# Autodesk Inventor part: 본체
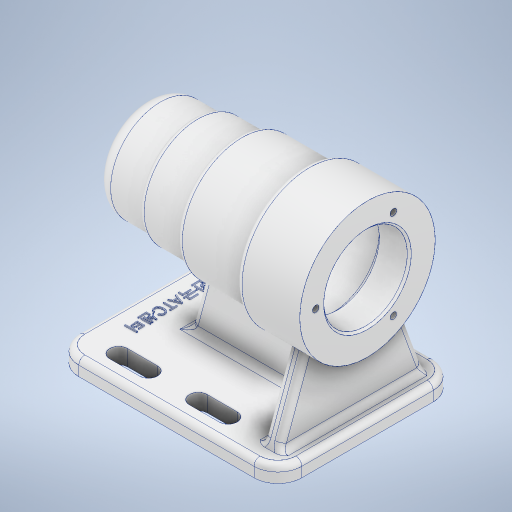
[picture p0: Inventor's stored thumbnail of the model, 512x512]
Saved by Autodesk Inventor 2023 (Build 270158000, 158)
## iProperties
Created: 2022-07
Part Number: 본체
Material: 알루미늄 6061
Document SubType Name: Modeling
Designer: owner
Density: 2.7 g/cm^3
Appearance: 알루미늄 - 평지
Author: owner
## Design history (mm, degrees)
sketch "스케치2"
  geometry: L1 (56, 34)-(24, 34); L2 (24, 34)-(24, 30); L3 (24, 30)-(-10, 30); L4 (-10, 30)-(-10, 27); L5 (-10, 27)-(-32, 27); L6 (-32, 27)-(-32, 25); L7 (-32, 25)-(-56, 25); L8 (-56, 0)-(56, 0); L9 (-56, 25)-(-56, 0); L10 (56, 34)-(56, 0); 4 further points
  constraints: 20 end point, 6 perpendicular, 3 midpoint, 2 coincident, 2 horizontal, 2 vertical
  dimensions: "d0" = 112 distance between parallel lines of L10 L9; "d1" = 80 distance from line of L9 point (24, 32); "d2" = 46 distance from line of L9 point (-10, 28.5); "d3" = 24 distance between parallel lines of L9 L6; "d4" = 68 diameter of L1 L8; "d5" = 60 diameter of L3 L8; "d6" = 54 diameter of L5 L8; "d7" = 50 diameter of L7 L8
revolve "회전1" sketch "스케치2" stored, may be unused: angle "d8" = 90 deg
sketch "스케치3"
  geometry: L1 (56, -34)-(56, 34) reference; L2 (56, 21)-(41, 21); L3 (41, 21)-(41, 24); L4 (41, 24)-(-13, 24); L5 (-13, 24)-(-13, 21); L6 (-13, 21)-(-25, 21); L7 (-25, 21)-(-25, 17.5); L8 (-25, 17.5)-(-43, 17.5); L9 (-55.978, 0)-(56, 0); L10 (-43, 17.5)-(-43, 16); L11 (-43, 16)-(-47, 16); L12 (-47, 16)-(-47, 10.5); L13 (-47, 10.5)-(-50, 10.5); L14 (-50, 10.5)-(-50, 0); 2 further points
  constraints: 26 end point, 9 perpendicular, 2 vertical, 1 horizontal, 1 midpoint, 1 point on line
  dimensions: "d9" = 15 distance of L2.start L2.end; "d10" = 54 distance of L3.end L4.end; "d11" = 12 distance of L5.end L6.end; "d12" = 18 distance of L7.end L8.end; "d13" = 42 diameter of L2 L9; "d16" = 48 diameter of L4 L9; "d19" = 35 diameter of L8 L9; "d20" = 42 diameter of L6 L9; "d21" = 21 diameter of L13 L9; "d22" = 32 diameter of L11 L9; "d23" = 3 distance of L12.end L13.end; "d24" = 4 distance of L10.end L11.end
revolve "회전2" sketch "스케치3" stored, may be unused: angle "d25" = 90 deg
node "작업 평면1"
sketch "스케치4"
  geometry: L1 (56, -45)-(-56, -45); L2 (-56, -45)-(-56, 45); L3 (-56, 45)-(56, 45); L4 (56, 45)-(56, -45); L5 (56, -45)-(-56, 45); L6 (-56, -45)-(56, 45); 1 further point
  constraints: 12 end point, 2 midpoint, 2 parallel, 1 horizontal, 1 perpendicular
  dimensions: "d27" = 112 distance of L2.end L3.end; "d28" = 90 distance of L1.end L2.end
extrude "돌출1" join sketch "스케치4" distance "d29" = 8; taper "d30" = 0 deg
node "작업 평면3"
sketch "스케치8"
  geometry: L1 (-23.409, -24.658)-(-37, -62); L2 (45, -62)-(-45, -62) reference; L3 (37, -62)-(23.409, -24.658); L4 (-37, -62)-(37, -62); L5 (45, -70)-(45, -62) reference; 6 further points
  constraints: 6 end point, 2 midpoint, 1 coincident, 1 collinear, 1 equal length, 1 point on line, 2 other
  dimensions: "d32" = 110 deg angle of L2 L3; "d33" = 110 deg angle of L2 L1; "d34" = 8 distance from line of L3.start L5
extrude "돌출2" join sketch "스케치8" distance "d35" = 8; taper "d36" = 0 deg
sketch "스케치11"
  geometry: L1 (48, -62)-(48, -24.658) reference; L2 (-10, -30)-(24, -30) reference; L3 (-32, -27)-(-10, -27) reference; L4 (-29, -62)-(-19.622, -27); L5 (-29, -62)-(48, -62); L6 (56, -62)-(-56, -62) reference; 1 further point
  constraints: 4 end point, 1 collinear, 1 point on line
  dimensions: "d41" = 77 distance of L4.start L1.start; "d42" = 105 deg angle of L6 L4
extrude "돌출3" join sketch "스케치11" stored distance "d44" = 8; taper "d45" = 0 deg
sketch "스케치12" dims "d54" = 52
  geometry: L1 (0, 0)-(13, 22.517); L2 (0, 0)-(-33.897, 0); C1 r 10.5 at (0, 0) reference; 1 further point
  constraints: 4 end point, 1 coincident, 1 horizontal, 3 other
  dimensions: "d56" = 120 deg angle of L1 L2
hole "구멍1" sketch "스케치12" at (13, 22.517) diameter "d46" = 3.242; stored, may be unused: countersink angle "d50" = 90 deg, drill point angle "d52" = 0 deg; dims "d47" = 8, "d48" = 4, "d49" = 2, "d51" = 11
sketch "스케치13"
  geometry: L1 (-56, 45)-(-56, -45) reference; L2 (56, -45)-(56, 45) reference; L3 (-40.5, 33)-(-16.5, 33); L4 (-36, 28.5)-(-21, 28.5); L5 (-21, 37.5)-(-36, 37.5); L6 (-56, 0)-(56, 0); L7 (-0.5, 33)-(23.5, 33); L8 (4, 37.5)-(19, 37.5); L9 (19, 28.5)-(4, 28.5); A1 r 4.5 centre (-36, 33) between (-36, 37.5) and (-36, 28.5); A2 r 4.5 centre (-21, 33) between (-21, 28.5) and (-21, 37.5); A3 r 4.5 centre (4, 33) between (4, 37.5) and (4, 28.5); A4 r 4.5 centre (19, 33) between (19, 28.5) and (19, 37.5); 3 further points
  constraints: 18 end point, 12 point on circle, 8 tangent, 4 centre point, 4 midpoint, 4 point on line, 2 horizontal, 2 parallel
  dimensions: "d60" = 20 distance from line of A1.centre L1; "d61" = 15 distance of A2.centre A1.centre; "d62" = 9 distance between parallel lines of L4 L5; "d63" = 33 distance from line of L6 point (-28.5, 33); "d64" = 15 distance of A4.centre A3.centre; "d65" = 9 distance between parallel lines of L9 L8; "d66" = 25 distance of A3.centre A2.centre; "d67" = 33 distance between parallel lines of L6 L7
extrude "돌출4" cut sketch "스케치13" extent not by distance; stored distance "d68" = 0; taper "d69" = 0 deg
sketch "스케치14"
  geometry: L1 (-56, 45)-(-56, -45) reference; 2 further points
  constraints: 1 horizontal alignment, 1 other
  dimensions: "d70" = 12 distance from line of L1 point (-44, 0)
feature "엠보싱1" sketch "스케치14" dims "d0" = 112, "d1" = 80, "d2" = 46, "d3" = 24, "d4" = 68, "d5" = 60, "d6" = 54, "d7" = 50, "d9" = 15, "d10" = 54, "d11" = 12, "d12" = 18, "d13" = 42, "d16" = 48, "d19" = 35, "d20" = 42, "d21" = 21, "d22" = 32, "d23" = 3, "d24" = 4, "d71" = 0.5, "d72" = 0
fillet "모깎기1" dims "d73" = 12
fillet "모깎기2" dims "d74" = 8, "d75" = 3
fillet "모깎기3" dims "d76" = 3
fillet "모깎기4" dims "d77" = 0.3
fillet "모깎기5" dims "d78" = 3
fillet "모깎기6" dims "d79" = 3
fillet "모깎기7" dims "d80" = 3
fillet "모깎기8" dims "d81" = 3
fillet "모깎기9" dims "d82" = 3
fillet "모깎기10" dims "d83" = 3
chamfer "모따기1" distance "d84" = 1; stored, may be unused: second distance "d85" = 2, angle "d86" = 45 deg
fillet "모깎기11" dims "d87" = 0.3
node "솔리드1"
pattern_circular "원형 패턴1" dims angle "d58" = 360 deg
mirror "미러1"
feature "A9D066F2-1C7D-4E18-AEED-F7BC21143FA4" dims "d46" = 3.242, "d47" = 8, "d48" = 4, "d49" = 2, "d50" = 90 deg, "d51" = 11, "d52" = 0
other parameters: "d31" = -8, "d43" = 8
